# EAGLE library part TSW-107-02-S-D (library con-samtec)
THROUGH-HOLE .025" SQ POST HEADER Source: Samtec TSW.pdf
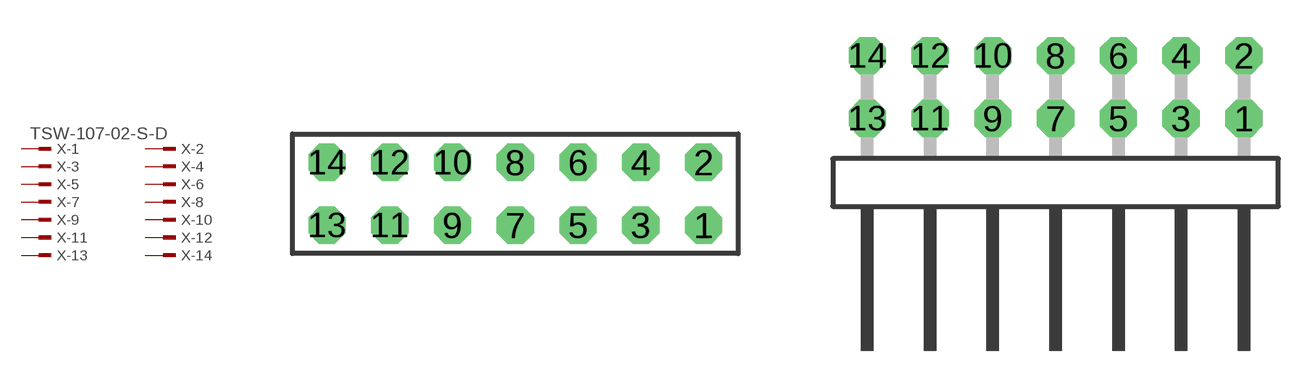
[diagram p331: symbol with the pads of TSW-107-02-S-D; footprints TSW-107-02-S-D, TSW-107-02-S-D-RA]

Designator prefix X; gates -1=MPINV -2=MPIN -3=MPIN -4=MPIN -5=MPIN -6=MPIN -7=MPIN -8=MPIN -9=MPIN -10=MPIN -11=MPIN -12=MPIN -13=MPIN -14=MPIN

## TSW-107-02-S-D (OC_FARNELL: unknown; OC_NEWARK: unknown)  [TSW-107-02-S-D]
1  -1:1  pas
2  -2:1  pas
3  -3:1  pas
4  -4:1  pas
5  -5:1  pas
6  -6:1  pas
7  -7:1  pas
8  -8:1  pas
9  -9:1  pas
10  -10:1  pas
11  -11:1  pas
12  -12:1  pas
13  -13:1  pas
14  -14:1  pas

## TSW-107-02-S-D-RA (OC_FARNELL: unknown; OC_NEWARK: unknown)  [TSW-107-02-S-D-RA]
Pads as for TSW-107-02-S-D

## Footprint TSW-107-02-S-D (pad centres in mm)
THROUGH-HOLE .025" SQ POST HEADER Source: Samtec TSW.pdf
drill 1 pad 1.5 octagon: 1 7.62,-1.27; 2 7.62,1.27; 3 5.08,-1.27; 4 5.08,1.27; 5 2.54,-1.27; 6 2.54,1.27; 7 0,-1.27; 8 0,1.27; 9 -2.54,-1.27; 10 -2.54,1.27; 11 -5.08,-1.27; 12 -5.08,1.27; 13 -7.62,-1.27; 14 -7.62,1.27

## Footprint TSW-107-02-S-D-RA (pad centres in mm)
THROUGH-HOLE .025" SQ POST HEADER Source: Samtec TSW.pdf
drill 1 pad 1.5 octagon: 1 7.62,1.524; 2 7.62,4.064; 3 5.08,1.524; 4 5.08,4.064; 5 2.54,1.524; 6 2.54,4.064; 7 0,1.524; 8 0,4.064; 9 -2.54,1.524; 10 -2.54,4.064; 11 -5.08,1.524; 12 -5.08,4.064; 13 -7.62,1.524; 14 -7.62,4.064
